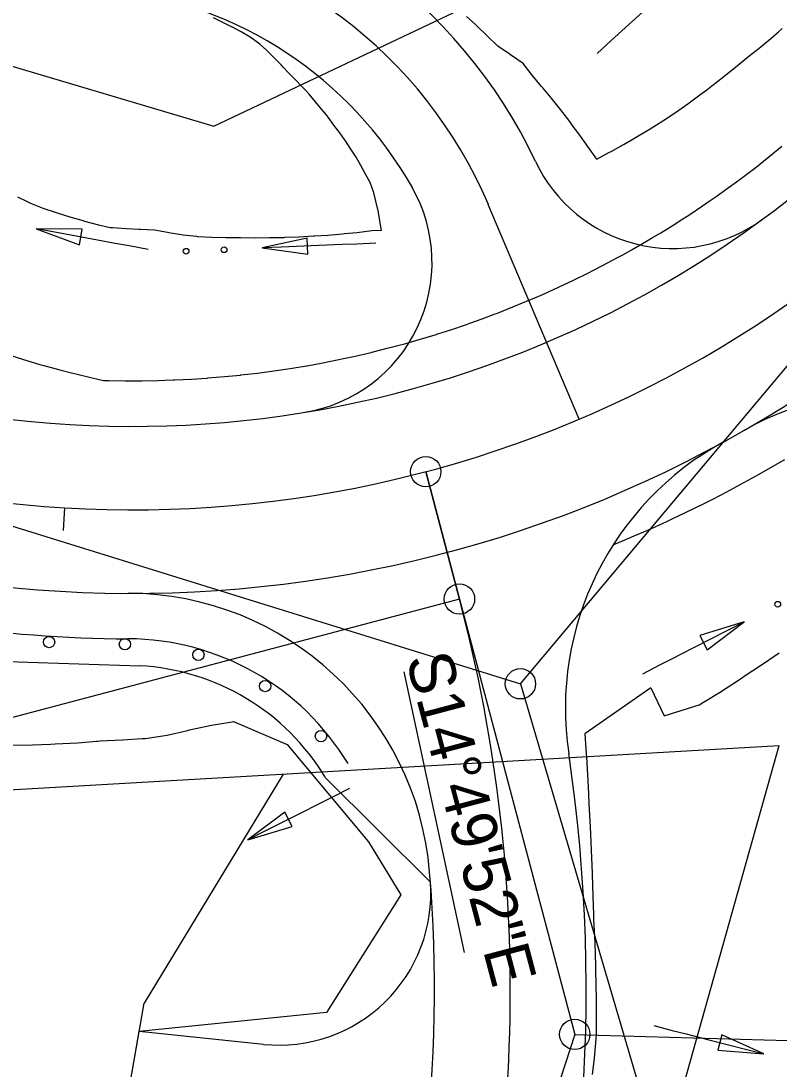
# Model space of a CAD drawing. Extents: x 1 to 1477871, y 1 to 1872901.
# Drawn here: x 1443923.9 to 1444023.8, y 1854893.5 to 1855031.6 of the extents above; entities that cross this region are included whole.
import ezdxf

# ---------------------------------------------------------------- set-up
doc = ezdxf.new("R2010")
doc.units = 0
for name, color, linetype in [('R_Drive', 7, 'Continuous'), ('R_Floodplain', 7, 'Continuous'), ('R_Horz Alg', 7, 'Continuous'), ('R_Horz Alg Annot', 7, 'Continuous'), ('R_No Plot', 7, 'Continuous'), ('R_Proposed Const Limits_Cut', 7, 'Continuous'), ('R_Proposed Const Limits_Fill', 7, 'Continuous'), ('R_Proposed Road_Lane', 7, 'Continuous'), ('R_Proposed Road_Shoulder', 7, 'Continuous'), ('R_ROW', 7, 'Continuous'), ('R_Steel', 7, 'Continuous'), ('R_Temp Easement', 7, 'Continuous'), ('R_Water', 7, 'Continuous')]:
    doc.layers.add(name, color=color, linetype=linetype)

msp = doc.modelspace()

# ---------------------------------------------------------------- linework, layer by layer
at = {"layer": 'R_Drive'}
for p in [(1443936.07, 1854878.66), (1443955.87, 1854896.73)]:
    msp.add_line(p, (1443939.47, 1854898.41), dxfattribs=at)
for centre, radius, start, end in [((1443930.24, 1854983.97), 68, 25.3079, 83.4809), ((1443930.24, 1854983.97), 52, 29.5544, 83.4809), ((1444009.79, 1855021.59), 20, 205.3079, 306.4415), ((1443958.07, 1854999.75), 20, 279.336, 29.5544), ((1443957.91, 1854916.63), 20, 264.1498, 4.2517)]:
    msp.add_arc(centre, radius, start, end, dxfattribs=at)
at = {"layer": 'R_Floodplain'}
msp.add_open_spline([(1444534.23, 1857777.84), (1444398.78, 1857609.12), (1444367.89, 1857131.47), (1444306.1, 1856808.28), (1444134.95, 1856378.26), (1444024.62, 1856227.92), (1443837.91, 1855964.82), (1443664.53, 1855852.06), (1443479.03, 1855867.82), (1443335.96, 1855886.01), (1443298.37, 1855854.49), (1443356.57, 1855756.28), (1443606.51, 1855482.27), (1443757.19, 1855307.33), (1443863.11, 1855113.58), (1443878.59, 1855007.91), (1443849.87, 1854910.07), (1443760.66, 1854753.08), (1443429.28, 1854512.04), (1443240.87, 1854371.16), (1443115.26, 1854254.04), (1443060.94, 1853889.1), (1443099.99, 1853680.31), (1443032.09, 1853386.66), (1443001.54, 1853198.25), (1444534.23, 1857777.84), (1443001.54, 1853198.25)], degree=3, dxfattribs=at)
at = {"layer": 'R_Horz Alg'}
for p, q in [((1443981.68, 1854955.41), (1443977.24, 1854972.19)), ((1443977.24, 1854972.19), (1443981.68, 1854955.41))]:
    msp.add_line(p, q, dxfattribs=at)
for centre, radius, start, end in [((1443938.64, 1855117.94), 150.78, 252.7667, 320), ((1443938.64, 1855117.94), 150.78, 252.7667, 320), ((1443787.34, 1854903.95), 201.04, 341.9445, 14.8311), ((1443787.34, 1854903.95), 201.04, 341.9445, 14.8311)]:
    msp.add_arc(centre, radius, start, end, dxfattribs=at)
at = {"layer": 'R_Horz Alg Annot'}
for p, q in [((1443989.71, 1854944.24), (1444054.15, 1855021.02)), ((1443893.97, 1854973.93), (1443989.71, 1854944.24)), ((1443981.68, 1854955.41), (1443996.87, 1854898.05)), ((1443996.87, 1854898.05), (1443978.48, 1854841.64))]:
    msp.add_line(p, q, dxfattribs=at)
for points in [[(1443929.5, 1854964.44), (1443929.68, 1854967.43)], [(1443981.68, 1854955.41), (1443830.71, 1854915.43)], [(1443989.71, 1854944.24), (1444023.56, 1854829.11)], [(1443996.87, 1854898.05), (1444106.02, 1854894.98)]]:
    msp.add_lwpolyline(points, dxfattribs=at)
for centre in [(1443977.24, 1854972.19), (1443981.68, 1854955.41), (1443989.71, 1854944.24), (1443996.87, 1854898.05)]:
    msp.add_circle(centre, 2, dxfattribs=at)
at = {"layer": 'R_No Plot'}
msp.add_line((1443997.46, 1854979.11), (1443985.48, 1855007.37), dxfattribs=at)
msp.add_arc((1443930.24, 1854983.97), 60, 22.959, 83.4809, dxfattribs=at)
at = {"layer": 'R_Proposed Const Limits_Cut'}
for points in [[(1443923.45, 1855008.39), (1443924.71, 1855007.78), (1443925.16, 1855007.56), (1443926.91, 1855006.85), (1443928.28, 1855006.41), (1443928.69, 1855006.28), (1443930.48, 1855005.73), (1443931.93, 1855005.31), (1443932.29, 1855005.21), (1443934.11, 1855004.72), (1443935.65, 1855004.38), (1443935.76, 1855004.36), (1443935.95, 1855004.35), (1443937.8, 1855004.23), (1443939.42, 1855004.14), (1443939.65, 1855004.13), (1443941.51, 1855004.03), (1443943.21, 1855003.73), (1443943.38, 1855003.7), (1443945.27, 1855003.41), (1443947.05, 1855003.21), (1443947.16, 1855003.19), (1443949.05, 1855003.1), (1443950.9, 1855003.05), (1443950.94, 1855003.05), (1443952.84, 1855003.03), (1443954.75, 1855003.01), (1443954.78, 1855003.01), (1443956.66, 1855003.02), (1443958.58, 1855003.06), (1443958.67, 1855003.07), (1443960.5, 1855003.14), (1443962.43, 1855003.24), (1443962.58, 1855003.25), (1443964.35, 1855003.37), (1443966.28, 1855003.53), (1443966.51, 1855003.55), (1443968.21, 1855003.72), (1443970.15, 1855003.95), (1443971.39, 1855004.02)], [(1444006.9, 1854943.71), (1444008.64, 1854940.01), (1444013.26, 1854941.47), (1444014.04, 1854941.94), (1444015.95, 1854943.11), (1444018.59, 1854944.82), (1444019.44, 1854945.4), (1444021.21, 1854946.55), (1444023.79, 1854948.32)], [(1443974.33, 1854945.82), (1443982.3, 1854908.82)]]:
    msp.add_lwpolyline(points, dxfattribs=at)
at = {"layer": 'R_Proposed Const Limits_Fill'}
for points in [[(1443971.39, 1855004.02), (1443971.25, 1855004.93), (1443971.19, 1855005.28), (1443970.95, 1855006.54), (1443970.67, 1855007.81), (1443970.39, 1855008.91), (1443970.35, 1855009.07), (1443969.9, 1855010.27), (1443969.32, 1855011.4), (1443968.7, 1855012.51), (1443968.69, 1855012.54), (1443968.06, 1855013.61), (1443967.38, 1855014.7), (1443966.67, 1855015.77), (1443966.53, 1855015.96), (1443965.92, 1855016.81), (1443965.13, 1855017.83), (1443964.37, 1855018.89), (1443964.1, 1855019.24), (1443963.56, 1855019.92), (1443962.73, 1855020.93), (1443961.87, 1855021.92), (1443961.43, 1855022.41), (1443960.97, 1855022.9), (1443960.05, 1855023.85), (1443959.1, 1855024.78), (1443958.49, 1855025.42), (1443958.17, 1855025.77), (1443957.22, 1855026.75), (1443956.24, 1855027.71), (1443955.42, 1855028.46), (1443955.22, 1855028.64), (1443954.11, 1855029.44), (1443952.94, 1855030.12), (1443951.78, 1855030.74), (1443951.74, 1855030.77), (1443950.52, 1855031.38), (1443949.29, 1855031.97)], [(1443999.8, 1855013.38), (1443997.41, 1855016.71), (1443996.54, 1855017.85), (1443996.21, 1855018.31), (1443995.01, 1855019.89), (1443993.77, 1855021.43), (1443992.65, 1855022.74), (1443992.49, 1855022.92), (1443991.27, 1855024.44), (1443990.08, 1855025.97), (1443988.41, 1855027.13), (1443988.36, 1855027.16), (1443986.72, 1855028.24), (1443985.37, 1855029.58), (1443984.01, 1855030.9), (1443983.75, 1855031.14), (1443982.61, 1855032.17)], [(1443999.8, 1855013.38), (1444001.38, 1855014.23), (1444001.67, 1855014.38), (1444003.4, 1855015.34), (1444004.2, 1855015.8), (1444005.11, 1855016.33), (1444006.81, 1855017.35), (1444007.65, 1855017.87), (1444008.49, 1855018.41), (1444010.13, 1855019.52), (1444011, 1855020.12), (1444011.76, 1855020.65), (1444013.37, 1855021.82), (1444014.27, 1855022.49), (1444014.95, 1855023.01), (1444016.52, 1855024.24), (1444017.45, 1855024.98), (1444018.06, 1855025.48), (1444019.59, 1855026.75), (1444020.6, 1855027.53), (1444021.17, 1855027.98), (1444022.69, 1855029.27), (1444023.7, 1855030.15), (1444024.19, 1855030.58)], [(1444006.9, 1854943.71), (1443998.19, 1854937.63), (1443998.38, 1854935.03), (1443998.41, 1854934.57), (1443998.59, 1854931.5), (1443998.67, 1854929.72), (1443998.73, 1854928.44), (1443998.9, 1854925.39), (1443998.95, 1854924.43), (1443999.05, 1854922.34), (1443999.16, 1854919.29), (1443999.17, 1854919.14), (1443999.24, 1854916.24), (1443999.32, 1854913.86), (1443999.35, 1854913.2), (1443999.5, 1854910.16), (1443999.56, 1854908.59), (1443999.6, 1854907.11), (1443999.66, 1854904.07), (1443999.67, 1854903.31), (1443999.69, 1854901.02), (1443999.68, 1854898.03), (1443999.68, 1854897.97), (1443999.41, 1854894.93), (1443999.18, 1854892.77)], [(1443922.44, 1854936.17), (1443925.42, 1854936.22), (1443927.82, 1854936.29), (1443928.4, 1854936.31), (1443931.38, 1854936.48), (1443933.87, 1854936.69), (1443934.05, 1854936.7), (1443934.34, 1854936.71), (1443937.3, 1854936.85), (1443939.88, 1854937.02), (1443940.25, 1854937.05), (1443943.19, 1854937.48), (1443945.84, 1854938.09), (1443946.1, 1854938.16), (1443949, 1854938.78), (1443951.74, 1854939.23), (1443951.9, 1854939.26), (1443959, 1854936.26)], [(1443959, 1854936.26), (1443969.68, 1854923.44), (1443973.94, 1854916.44)], [(1443973.94, 1854916.44), (1443964.18, 1854900.93), (1443939.47, 1854898.41), (1443939.47, 1854898.41)]]:
    msp.add_lwpolyline(points, dxfattribs=at)
at = {"layer": 'R_Proposed Road_Lane'}
for centre, radius, start, end in [((1443938.64, 1855117.94), 139.78, 252.7667, 320), ((1443938.64, 1855117.94), 161.78, 252.7667, 320), ((1444038.75, 1854942.75), 40, 44.0911, 119.744), ((1444035.63, 1854941), 40, 118.7283, 188.4876), ((1443937.88, 1854916.17), 40, 4.6393, 89.7843), ((1443787.34, 1854903.95), 211.04, 341.9445, 8.4876), ((1443787.34, 1854903.95), 191.04, 341.9445, 4.6393)]:
    msp.add_arc(centre, radius, start, end, dxfattribs=at)
at = {"layer": 'R_Proposed Road_Shoulder'}
for p, q in [((1443906.42, 1854947.69), (1443939.55, 1854946.62)), ((1443964, 1854931.91), (1443977.85, 1854918.11))]:
    msp.add_line(p, q, dxfattribs=at)
for points in [[(1443922.71, 1854987.46), (1443924.8, 1854986.81), (1443926.41, 1854986.33), (1443926.9, 1854986.19), (1443929.02, 1854985.61), (1443930.73, 1854985.17), (1443931.15, 1854985.06), (1443933.3, 1854984.55), (1443934.77, 1854984.22), (1443935.12, 1854984.21), (1443935.47, 1854984.2), (1443937.65, 1854984.17), (1443939.56, 1854984.17), (1443939.83, 1854984.17), (1443942.01, 1854984.21), (1443942.86, 1854984.23), (1443943.99, 1854984.27), (1443944.19, 1854984.28), (1443946.37, 1854984.39), (1443948.42, 1854984.52), (1443948.54, 1854984.53), (1443950.72, 1854984.71), (1443952.84, 1854984.92), (1443952.88, 1854984.93), (1443955.05, 1854985.17), (1443957.21, 1854985.46), (1443957.24, 1854985.46), (1443959.37, 1854985.78), (1443961.52, 1854986.14), (1443961.62, 1854986.15), (1443963.67, 1854986.53), (1443965.8, 1854986.95), (1443965.98, 1854986.99), (1443967.93, 1854987.41), (1443970.06, 1854987.91), (1443970.31, 1854987.97), (1443972.17, 1854988.44), (1443974.28, 1854989), (1443974.6, 1854989.09), (1443976.38, 1854989.6), (1443978.46, 1854990.23), (1443978.85, 1854990.35), (1443980.54, 1854990.89), (1443982.6, 1854991.59), (1443983.06, 1854991.75), (1443984.66, 1854992.33), (1443986.39, 1854992.98), (1443986.7, 1854993.09), (1443987.22, 1854993.3), (1443988.73, 1854993.89), (1443990.74, 1854994.73), (1443991.32, 1854994.97), (1443992.74, 1854995.59), (1443994.73, 1854996.49), (1443995.37, 1854996.79), (1443996.7, 1854997.42), (1443998.66, 1854998.38), (1443999.36, 1854998.74), (1444000.6, 1854999.38), (1444002.52, 1855000.4), (1444003.28, 1855000.81), (1444004.43, 1855001.46), (1444006.32, 1855002.55), (1444007.12, 1855003.02), (1444007.89, 1855003.48), (1444008.19, 1855003.66), (1444010.04, 1855004.81), (1444010.9, 1855005.36), (1444011.88, 1855005.99), (1444013.69, 1855007.2), (1444014.59, 1855007.81), (1444015.49, 1855008.44), (1444017.26, 1855009.7), (1444018.2, 1855010.39), (1444019.02, 1855011), (1444020.75, 1855012.32), (1444021.72, 1855013.09), (1444022.46, 1855013.68), (1444024.15, 1855015.06)], [(1444001.94, 1854962.57), (1444003.98, 1854963.41), (1444004.71, 1854963.72), (1444006.49, 1854964.5), (1444008.98, 1854965.62), (1444009.79, 1854966), (1444011.46, 1854966.79), (1444013.91, 1854968), (1444014.79, 1854968.44), (1444016.34, 1854969.24), (1444018.76, 1854970.53), (1444019.7, 1854971.05), (1444021.15, 1854971.85), (1444023.52, 1854973.22), (1444024.53, 1854973.81)]]:
    msp.add_lwpolyline(points, dxfattribs=at)
msp.add_arc((1443937.88, 1854916.17), 30.5, 31.0835, 86.867, dxfattribs=at)
at = {"layer": 'R_ROW'}
for p, q in [((1443565.8, 1855131.35), (1443949.34, 1855017.73)), ((1443949.34, 1855017.73), (1444008.81, 1855045.93)), ((1443895.27, 1854928.7), (1444023.78, 1854936.11))]:
    msp.add_line(p, q, dxfattribs=at)
at = {"layer": 'R_Steel'}
for centre in [(1443927.61, 1854949.74), (1443937.61, 1854949.45), (1443947.28, 1854948.06), (1443956.08, 1854943.94), (1443963.44, 1854937.35)]:
    msp.add_circle(centre, 0.75, dxfattribs=at)
for centre, radius, start, end in [((1443938.64, 1855117.94), 167.78, 252.7667, 269.7843), ((1443937.88, 1854916.17), 34, 31.0835, 89.7843)]:
    msp.add_arc(centre, radius, start, end, dxfattribs=at)
at = {"layer": 'R_Temp Easement'}
for p, q in [((1443981.03, 1854783.84), (1444023.78, 1854936.11)), ((1443958.45, 1854932.34), (1443940.12, 1854902.17)), ((1443935.47, 1854875.19), (1443940.12, 1854902.17))]:
    msp.add_line(p, q, dxfattribs=at)
at = {"layer": 'R_Water'}
for p, q in [((1443925.9, 1855004.19), (1443931.61, 1855002.06)), ((1443931.99, 1855004.15), (1443925.9, 1855004.19)), ((1443931.61, 1855002.06), (1443931.99, 1855004.15)), ((1443961.62, 1855002.97), (1443955.67, 1855001.67)), ((1443961.71, 1855000.86), (1443961.62, 1855002.97)), ((1443955.67, 1855001.67), (1443961.71, 1855000.86)), ((1444019.17, 1854952.41), (1444013.34, 1854950.62)), ((1444014.31, 1854948.73), (1444019.17, 1854952.41)), ((1444013.34, 1854950.62), (1444014.31, 1854948.73)), ((1443958.69, 1854927.33), (1443953.81, 1854923.68)), ((1443959.64, 1854925.44), (1443958.69, 1854927.33)), ((1443953.81, 1854923.68), (1443959.64, 1854925.44)), ((1444016.26, 1854898), (1444015.73, 1854895.95)), ((1444021.8, 1854895.48), (1444016.26, 1854898)), ((1444015.73, 1854895.95), (1444021.8, 1854895.48))]:
    msp.add_line(p, q, dxfattribs=at)
for points in [[(1443999.82, 1855027.3), (1444001.68, 1855028.99), (1444003.08, 1855030.26), (1444005.37, 1855032.34), (1444009.06, 1855035.69), (1444010.93, 1855037.38)], [(1443940.65, 1855001.48), (1443938.17, 1855001.93), (1443936.32, 1855002.27), (1443933.27, 1855002.83), (1443928.37, 1855003.74), (1443925.9, 1855004.19)], [(1443970.66, 1855002.29), (1443968.14, 1855002.18), (1443966.26, 1855002.1), (1443963.16, 1855001.98), (1443958.18, 1855001.77), (1443955.67, 1855001.67)], [(1444005.82, 1854945.57), (1444008.06, 1854946.72), (1444009.73, 1854947.58), (1444012.49, 1854948.99), (1444016.93, 1854951.26), (1444019.17, 1854952.41)], [(1443967.2, 1854930.44), (1443964.95, 1854929.3), (1443963.27, 1854928.45), (1443960.5, 1854927.06), (1443956.05, 1854924.81), (1443953.81, 1854923.68)], [(1444007.27, 1854899.2), (1444009.71, 1854898.58), (1444011.54, 1854898.11), (1444014.54, 1854897.34), (1444019.37, 1854896.1), (1444021.8, 1854895.48)]]:
    msp.add_lwpolyline(points, dxfattribs=at)
for centre in [(1443945.67, 1855001.23), (1443950.67, 1855001.43), (1444023.61, 1854954.72)]:
    msp.add_circle(centre, 0.375, dxfattribs=at)

# ---------------------------------------------------------------- texts
at = {"layer": 'R_Horz Alg Annot'}
msp.add_text('S14%%d49\'52"E', height=6, rotation=284.8311, dxfattribs=at).set_placement((1443974.59, 1854947.54))

doc.saveas('drawing.dxf')
